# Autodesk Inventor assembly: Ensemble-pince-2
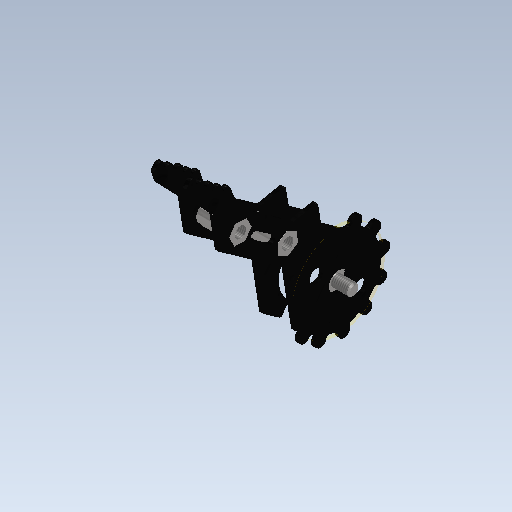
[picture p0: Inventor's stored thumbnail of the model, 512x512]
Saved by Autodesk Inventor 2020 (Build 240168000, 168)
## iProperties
Created: 2021-10
Part Number: Ensemble-pince-2
Document SubType Name: Assembly
Designer: bruno
Author: bruno
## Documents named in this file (4)
- C:\Users\bruno\OneDrive\Bureau\Robot-Inventor\Pince-Inventor\Ensemble-pince-2.iam
- C:\Users\bruno\OneDrive\Bureau\Robot-Inventor\Pince-Inventor\Ensemble-doigt-2.iam
- C:\Users\bruno\OneDrive\Bureau\Robot-Inventor\Pince-Inventor\pince-2.ipt
- C:\Users\bruno\Documents\Inventor\Content Center Files\R2020\fr-FR\ANSI B18.6.7M(01)\ANSI B18.6.7M - M3x0,5 x 5(5).ipt
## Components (5 placed, 3 different names)
1. Ensemble-doigt-2:1 [sub-assembly] — Logement:1, Angle:1, Placage:5, Placage:6
2. pince-2:1 — Logement:1, Angle:1, Placage:1, Placage:2, Placage:3, Placage:4
3. Vis à tête tronconique à empreinte cruciforme - Type IA - Métrique M3x0,5 x 5:1 — Placage:1, Placage:2
4. Vis à tête tronconique à empreinte cruciforme - Type IA - Métrique M3x0,5 x 5:2 — Placage:3, Placage:4
5. Vis à tête tronconique à empreinte cruciforme - Type IA - Métrique M3x0,5 x 5:3 — Placage:5, Placage:6
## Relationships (8: Mate 6, Insert 1, Angle 1)
- Logement:1 [Insert]: Ensemble-doigt-2:1 ↔ pince-2:1
- Angle:1: Ensemble-doigt-2:1 ↔ pince-2:1
- Placage:1 [Mate]: pince-2:1 ↔ Vis à tête tronconique à empreinte cruciforme - Type IA - Métrique M3x0,5 x 5:1
- Placage:2 [Mate]: pince-2:1 ↔ Vis à tête tronconique à empreinte cruciforme - Type IA - Métrique M3x0,5 x 5:1
- Placage:3 [Mate]: pince-2:1 ↔ Vis à tête tronconique à empreinte cruciforme - Type IA - Métrique M3x0,5 x 5:2
- Placage:4 [Mate]: pince-2:1 ↔ Vis à tête tronconique à empreinte cruciforme - Type IA - Métrique M3x0,5 x 5:2
- Placage:5 [Mate]: Ensemble-doigt-2:1 ↔ Vis à tête tronconique à empreinte cruciforme - Type IA - Métrique M3x0,5 x 5:3
- Placage:6 [Mate]: Ensemble-doigt-2:1 ↔ Vis à tête tronconique à empreinte cruciforme - Type IA - Métrique M3x0,5 x 5:3
